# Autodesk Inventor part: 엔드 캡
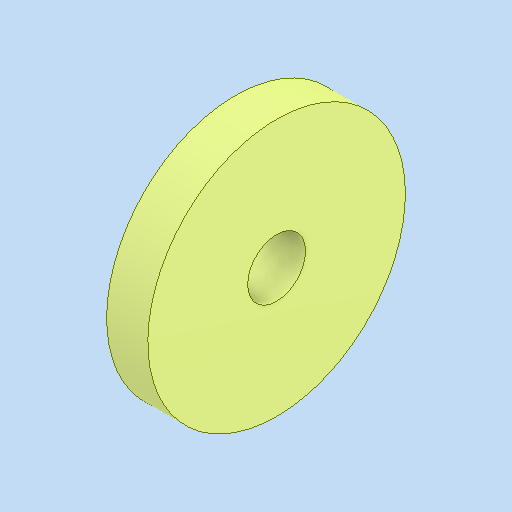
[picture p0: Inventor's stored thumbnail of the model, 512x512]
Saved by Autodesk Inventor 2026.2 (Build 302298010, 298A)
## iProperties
Created: 2026-03
Part Number: 엔드 캡
Material: 강철, 연강
Document SubType Name: Modeling
Designer: PC-2-03
Density: 7.85 g/cm^3
Appearance: 기본값
Author: jhkim
Sending System: Autodesk Inventor 2026
Preprocessor: ST-DEVELOPER v20.1
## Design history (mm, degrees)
feature "솔리드1"
node "솔리드2"
